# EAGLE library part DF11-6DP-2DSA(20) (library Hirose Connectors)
CONN, VERT, PTH, 6P, 3x2, 2mm PITCH
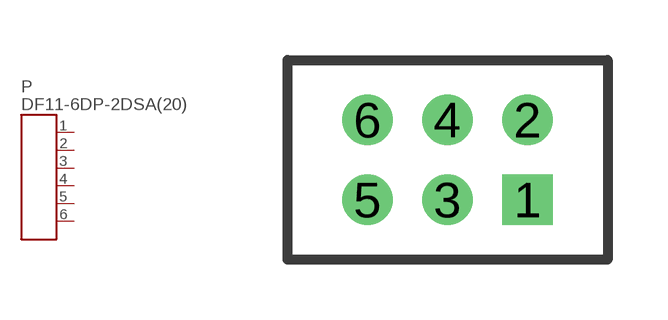
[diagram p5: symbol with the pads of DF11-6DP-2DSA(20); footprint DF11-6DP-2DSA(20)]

Designator prefix P

## DF11-6DP-2DSA(20)  [DF11-6DP-2DSA(20)]
1  P$1
2  P$2
3  P$3
4  P$4
5  P$5
6  P$6

## Footprint DF11-6DP-2DSA(20) (pad centres in mm)
drill 0.737 pad 1.27 square: 1 2,-1
drill 0.737 pad 1.27 round: 2 2,1; 3 0,-1; 4 0,1; 5 -2,-1; 6 -2,1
